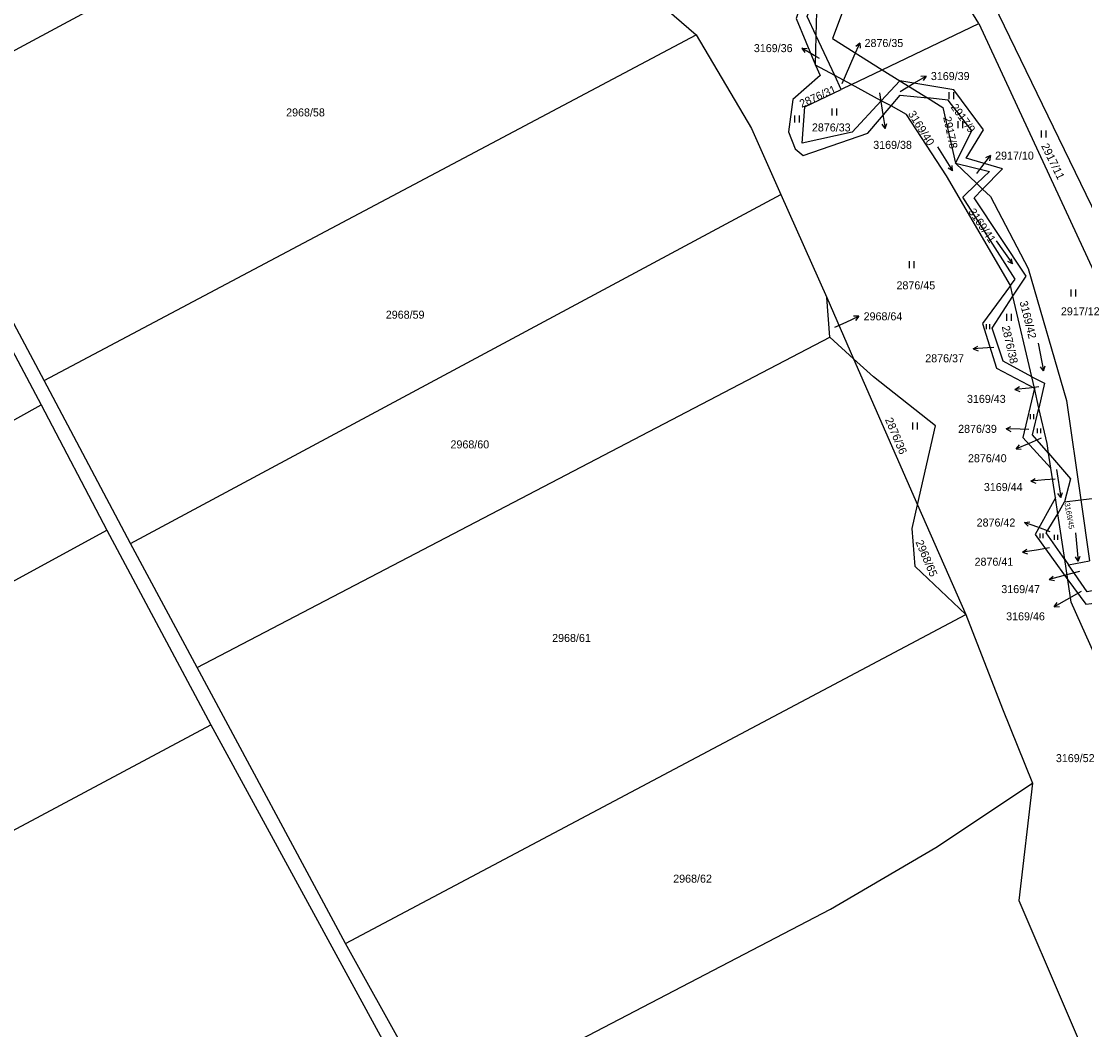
# Model space of a CAD drawing. Extents: x -776734 to -748832, y -1118122 to -976986.
# Drawn here: x -754304.9 to -754079.1, y -1114445.3 to -1114231.2 of the extents above; entities that cross this region are included whole.
import ezdxf

# ---------------------------------------------------------------- set-up
doc = ezdxf.new("R2010")
doc.units = 0
for name, color, linetype in [('KM_Hranice parcel', 7, 'Continuous'), ('KM_Parcelní čísla', 7, 'Continuous'), ('KM_Pop  PČ popisy', 7, 'Continuous'), ('KM_Značky kultur', 7, 'Continuous')]:
    doc.layers.add(name, color=color, linetype=linetype)

msp = doc.modelspace()

# ---------------------------------------------------------------- linework, layer by layer
at = {"layer": 'KM_Hranice parcel'}
for p, q in [((-754330.63, -1114250.42), (-754198.85, -1114179.51)), ((-754101.58, -1114231.65), (-754111.21, -1114215.97)), ((-754122.1, -1114241.5), (-754101.58, -1114231.65)), ((-754101.58, -1114231.65), (-754070.44, -1114298.96)), ((-754300.04, -1114307.5), (-754161.66, -1114234.11)), ((-754136.28, -1114240.53), (-754136.12, -1114234.32)), ((-754132.18, -1114242.74), (-754136.12, -1114234.32)), ((-754132.18, -1114242.74), (-754136.28, -1114240.53)), ((-754130.81, -1114245.67), (-754132.18, -1114242.74)), ((-754128.66, -1114244.64), (-754132.18, -1114242.74)), ((-754128.66, -1114244.64), (-754122.1, -1114241.5)), ((-754122.1, -1114241.5), (-754118.39, -1114243.82)), ((-754128.66, -1114244.64), (-754130.81, -1114245.67)), ((-754122.32, -1114248.07), (-754128.66, -1114244.64)), ((-754122.32, -1114248.07), (-754118.39, -1114243.82)), ((-754118.39, -1114243.82), (-754112.53, -1114247.49)), ((-754120.24, -1114249.19), (-754122.32, -1114248.07)), ((-754300.04, -1114307.5), (-754330.63, -1114250.42)), ((-754142.02, -1114254.7), (-754140.64, -1114258.27)), ((-754106.55, -1114261.3), (-754102, -1114265.68)), ((-754102, -1114265.68), (-754100.8, -1114266.84)), ((-754281.75, -1114342.09), (-754143.64, -1114268.01)), ((-754143.64, -1114268.01), (-754133.91, -1114289.88)), ((-754318.37, -1114279.49), (-754300.68, -1114312.68)), ((-754094.36, -1114289.61), (-754094.89, -1114287.34)), ((-754133.91, -1114289.88), (-754128.21, -1114302.87)), ((-754133.22, -1114298.26), (-754133.91, -1114289.88)), ((-754090.38, -1114306.73), (-754094.36, -1114289.61)), ((-754267.57, -1114368.44), (-754133.22, -1114298.26)), ((-754128.21, -1114302.87), (-754133.22, -1114298.26)), ((-754128.21, -1114302.87), (-754114.6, -1114333.87)), ((-754089.82, -1114309.14), (-754090.38, -1114306.73)), ((-754281.75, -1114342.09), (-754300.04, -1114307.5)), ((-754088.84, -1114313.35), (-754089.82, -1114309.14)), ((-754420.74, -1114378.33), (-754300.68, -1114312.68)), ((-754300.68, -1114312.68), (-754286.74, -1114339.26)), ((-754086.31, -1114326.08), (-754086.79, -1114322.92)), ((-754085.34, -1114332.43), (-754086.31, -1114326.08)), ((-754079.94, -1114332.85), (-754065.07, -1114330.98)), ((-754114.6, -1114333.87), (-754104.37, -1114357.19)), ((-754084.83, -1114335.76), (-754085.34, -1114332.43)), ((-754084.83, -1114335.76), (-754083.39, -1114333.28)), ((-754083.39, -1114333.28), (-754079.94, -1114332.85)), ((-754079.94, -1114332.85), (-754078.08, -1114345.79)), ((-754083.35, -1114345.47), (-754084.83, -1114335.76)), ((-754403.13, -1114402.7), (-754286.74, -1114339.26)), ((-754286.74, -1114339.26), (-754264.71, -1114380.62)), ((-754267.57, -1114368.44), (-754281.75, -1114342.09)), ((-754083.35, -1114345.47), (-754082.54, -1114346.65)), ((-754082.69, -1114349.83), (-754083.35, -1114345.47)), ((-754082.54, -1114346.65), (-754078.08, -1114345.79)), ((-754236.07, -1114427.01), (-754104.37, -1114357.19)), ((-754236.07, -1114427.01), (-754267.57, -1114368.44)), ((-754382.26, -1114443.46), (-754264.71, -1114380.62)), ((-754264.71, -1114380.62), (-754222.71, -1114457.49)), ((-754216.09, -1114463.01), (-754236.07, -1114427.01))]:
    msp.add_line(p, q, dxfattribs=at)
for points in [[(-754198.85, -1114179.51), (-754184.23, -1114198.03), (-754178.73, -1114219.2), (-754161.66, -1114234.11)], [(-754135.75, -1114198.57), (-754133.39, -1114209.08), (-754140.38, -1114230.64), (-754136.28, -1114240.53)], [(-754126, -1114206.49), (-754125.03, -1114209.47), (-754128.37, -1114223.34), (-754132.71, -1114234.86), (-754122.1, -1114241.5)], [(-754108.98, -1114205.82), (-754073.07, -1114279.85), (-754068.29, -1114298.13)], [(-754136.12, -1114234.32), (-754138.05, -1114230.19), (-754130.72, -1114210.04)], [(-754136.12, -1114234.32), (-754135.99, -1114229.21), (-754130.26, -1114212.66), (-754130.72, -1114210.04)], [(-754161.66, -1114234.11), (-754149.87, -1114253.99), (-754143.64, -1114268.01)], [(-754136.28, -1114240.53), (-754135.32, -1114242.74), (-754141.13, -1114247.79), (-754142.02, -1114254.7)], [(-754122.32, -1114248.07), (-754128.47, -1114254.73), (-754139.15, -1114257.08), (-754138.58, -1114249.4), (-754130.81, -1114245.67)], [(-754100.8, -1114266.84), (-754096.58, -1114262.54), (-754104.32, -1114260.28), (-754100.65, -1114254.25), (-754106.89, -1114245.75), (-754118.39, -1114243.82)], [(-754120.24, -1114249.19), (-754118.28, -1114246.9), (-754112.53, -1114247.49)], [(-754112.53, -1114247.49), (-754109.23, -1114249.55), (-754106.55, -1114261.3)], [(-754106.55, -1114261.3), (-754103.07, -1114254.47), (-754108.09, -1114247.94), (-754112.53, -1114247.49)], [(-754140.64, -1114258.27), (-754138.91, -1114259.72), (-754125.16, -1114254.96), (-754120.24, -1114249.19)], [(-754094.89, -1114287.34), (-754108.45, -1114264.04), (-754116.93, -1114250.98), (-754120.24, -1114249.19)], [(-754106.55, -1114261.3), (-754099.35, -1114263.1), (-754102, -1114265.68)], [(-754094.89, -1114287.34), (-754093.87, -1114285.98), (-754105, -1114268.59), (-754102, -1114265.68)], [(-754094.36, -1114289.61), (-754091.54, -1114285.34), (-754102.61, -1114268.68), (-754100.8, -1114266.84)], [(-754100.8, -1114266.84), (-754099.14, -1114268.43), (-754091.14, -1114283.7), (-754082.96, -1114311.7), (-754079.94, -1114332.85)], [(-754094.89, -1114287.34), (-754100.85, -1114295.35), (-754097.82, -1114304.86), (-754089.82, -1114309.14)], [(-754090.38, -1114306.73), (-754096.42, -1114303.38), (-754098.81, -1114296.34), (-754094.36, -1114289.61)], [(-754114.6, -1114333.87), (-754110.82, -1114317.14), (-754123.96, -1114306.73), (-754128.21, -1114302.87)], [(-754090.38, -1114306.73), (-754087.64, -1114308.03), (-754088.84, -1114313.35)], [(-754089.82, -1114309.14), (-754092.26, -1114319.57), (-754086.31, -1114326.08)], [(-754086.79, -1114322.92), (-754090.2, -1114319), (-754088.84, -1114313.35)], [(-754086.79, -1114322.92), (-754087.1, -1114320.85), (-754088.84, -1114313.35)], [(-754086.79, -1114322.92), (-754082.11, -1114328.38), (-754083.39, -1114333.28)], [(-754104.37, -1114357.19), (-754115.09, -1114347.01), (-754115.75, -1114338.93), (-754114.6, -1114333.87)], [(-754085.34, -1114332.43), (-754089.64, -1114340.17), (-754082.69, -1114349.83)], [(-754083.35, -1114345.47), (-754087.3, -1114339.82), (-754084.83, -1114335.76)], [(-754077.18, -1114352.09), (-754078.63, -1114352.33), (-754082.54, -1114346.65)], [(-754070.12, -1114390.62), (-754071.69, -1114377.62), (-754081.98, -1114354.52), (-754082.69, -1114349.83)], [(-754082.69, -1114349.83), (-754078.88, -1114355.01), (-754076.45, -1114354.67)], [(-754104.37, -1114357.19), (-754096.56, -1114377.22), (-754090.24, -1114392.95)], [(-754216.09, -1114463.01), (-754133.11, -1114419.74), (-754110.77, -1114406.63), (-754090.24, -1114392.95)], [(-754090.24, -1114392.95), (-754093.11, -1114417.93), (-754074.27, -1114461.78), (-754076.46, -1114473.86), (-754097.61, -1114489.99), (-754140.24, -1114510.72), (-754161.36, -1114513.79), (-754175.88, -1114510.05), (-754180.4, -1114509.3)]]:
    msp.add_lwpolyline(points, dxfattribs=at)
at = {"layer": 'KM_Pop  PČ popisy'}
for p, q in [((-754136.6, -1114238.44), (-754139.172, -1114236.894)), ((-754139.172, -1114236.894), (-754138.056, -1114236.981)), ((-754139.172, -1114236.894), (-754138.572, -1114237.839)), ((-754128.07, -1114238.57), (-754126.849, -1114235.828)), ((-754126.849, -1114235.828), (-754127.714, -1114236.54)), ((-754126.849, -1114235.828), (-754126.799, -1114236.947)), ((-754135.46, -1114239.11), (-754136.6, -1114238.44)), ((-754130.65, -1114244.44), (-754128.07, -1114238.57)), ((-754115.38, -1114244.36), (-754112.781, -1114242.86)), ((-754112.781, -1114242.86), (-754113.899, -1114242.927)), ((-754112.781, -1114242.86), (-754113.398, -1114243.794)), ((-754118.34, -1114246.1), (-754115.38, -1114244.36)), ((-754122.68, -1114246.42), (-754121.96, -1114251)), ((-754121.96, -1114251), (-754121.491, -1114253.964)), ((-754121.491, -1114253.964), (-754122.142, -1114253.053)), ((-754121.491, -1114253.964), (-754121.153, -1114252.897)), ((-754100.97, -1114262.11), (-754099.164, -1114259.713)), ((-754099.164, -1114259.713), (-754100.167, -1114260.212)), ((-754099.164, -1114259.713), (-754099.367, -1114260.814)), ((-754102.05, -1114263.52), (-754100.97, -1114262.11)), ((-754132.17, -1114296.19), (-754129.8, -1114295.11)), ((-754129.8, -1114295.11), (-754127.08, -1114293.842)), ((-754127.08, -1114293.842), (-754128.199, -1114293.811)), ((-754127.08, -1114293.842), (-754127.776, -1114294.719)), ((-754102.794, -1114300.789), (-754101.83, -1114300.22)), ((-754099.8, -1114300.58), (-754102.794, -1114300.789)), ((-754102.794, -1114300.789), (-754101.76, -1114301.219)), ((-754098.4, -1114300.49), (-754099.8, -1114300.58)), ((-754093.935, -1114309.394), (-754092.991, -1114308.791)), ((-754090.95, -1114309.08), (-754093.935, -1114309.394)), ((-754088.87, -1114308.86), (-754090.95, -1114309.08)), ((-754093.935, -1114309.394), (-754092.886, -1114309.787)), ((-754095.811, -1114317.768), (-754094.8, -1114317.284)), ((-754092.81, -1114317.82), (-754095.811, -1114317.768)), ((-754095.811, -1114317.768), (-754094.818, -1114318.286)), ((-754090.96, -1114317.86), (-754092.81, -1114317.82)), ((-754088.38, -1114319.76), (-754090.95, -1114320.83)), ((-754090.95, -1114320.83), (-754093.712, -1114322.003)), ((-754093.712, -1114322.003), (-754092.986, -1114321.15)), ((-754093.712, -1114322.003), (-754092.595, -1114322.072)), ((-754090.57, -1114328.852), (-754089.616, -1114328.265)), ((-754087.58, -1114328.59), (-754090.57, -1114328.852)), ((-754090.57, -1114328.852), (-754089.528, -1114329.263)), ((-754085.39, -1114328.41), (-754087.58, -1114328.59)), ((-754091.88, -1114337.634), (-754090.768, -1114337.506)), ((-754089.06, -1114338.66), (-754091.88, -1114337.634)), ((-754091.88, -1114337.634), (-754091.11, -1114338.447)), ((-754086.46, -1114339.59), (-754089.06, -1114338.66)), ((-754086.6, -1114343.05), (-754089.36, -1114343.49)), ((-754092.324, -1114343.959), (-754091.413, -1114343.308)), ((-754089.36, -1114343.49), (-754092.324, -1114343.959)), ((-754092.324, -1114343.959), (-754091.257, -1114344.297)), ((-754083.75, -1114348.98), (-754086.649, -1114349.757)), ((-754086.649, -1114349.757), (-754085.811, -1114349.014)), ((-754086.649, -1114349.757), (-754085.552, -1114349.981)), ((-754080.2, -1114348.01), (-754083.75, -1114348.98)), ((-754083.01, -1114354.06), (-754085.609, -1114355.56)), ((-754079.88, -1114352.26), (-754083.01, -1114354.06)), ((-754085.609, -1114355.56), (-754084.992, -1114354.626)), ((-754085.609, -1114355.56), (-754084.491, -1114355.493))]:
    msp.add_line(p, q, dxfattribs=at)
at = {"layer": 'KM_Značky kultur'}
for p, q in [((-754107.881, -1114247.75), (-754107.881, -1114246.25)), ((-754106.88, -1114247.75), (-754106.88, -1114246.25)), ((-754132.731, -1114251.24), (-754132.731, -1114249.74)), ((-754131.73, -1114251.24), (-754131.73, -1114249.74)), ((-754140.691, -1114252.73), (-754140.691, -1114251.23)), ((-754139.69, -1114252.73), (-754139.69, -1114251.23)), ((-754106.001, -1114253.89), (-754106.001, -1114252.39)), ((-754105, -1114253.89), (-754105, -1114252.39)), ((-754088.321, -1114255.91), (-754088.321, -1114254.41)), ((-754087.32, -1114255.91), (-754087.32, -1114254.41)), ((-754110.358, -1114257.855), (-754107.178, -1114262.943)), ((-754107.178, -1114262.943), (-754108.121, -1114262.38)), ((-754107.178, -1114262.943), (-754107.271, -1114261.849)), ((-754097.928, -1114277.822), (-754094.486, -1114282.736)), ((-754094.486, -1114282.736), (-754094.636, -1114281.648)), ((-754116.351, -1114283.62), (-754116.351, -1114282.12)), ((-754115.35, -1114283.62), (-754115.35, -1114282.12)), ((-754094.486, -1114282.736), (-754095.458, -1114282.224)), ((-754082.021, -1114289.67), (-754082.021, -1114288.17)), ((-754081.02, -1114289.67), (-754081.02, -1114288.17)), ((-754095.671, -1114294.82), (-754095.671, -1114293.32)), ((-754094.67, -1114294.82), (-754094.67, -1114293.32)), ((-754099.962, -1114296.55), (-754099.962, -1114295.545)), ((-754099.292, -1114296.55), (-754099.292, -1114295.545)), ((-754088.988, -1114299.534), (-754087.843, -1114305.423)), ((-754087.843, -1114305.423), (-754088.521, -1114304.56)), ((-754087.843, -1114305.423), (-754087.537, -1114304.368)), ((-754090.632, -1114315.66), (-754090.632, -1114314.655)), ((-754089.962, -1114315.66), (-754089.962, -1114314.655)), ((-754115.631, -1114317.87), (-754115.631, -1114316.37)), ((-754114.63, -1114317.87), (-754114.63, -1114316.37)), ((-754089.142, -1114318.69), (-754089.142, -1114317.685)), ((-754088.472, -1114318.69), (-754088.472, -1114317.685)), ((-754085.135, -1114326.405), (-754084.196, -1114332.331)), ((-754084.196, -1114332.331), (-754084.845, -1114331.445)), ((-754084.196, -1114332.331), (-754083.854, -1114331.288)), ((-754088.582, -1114340.98), (-754088.582, -1114339.975)), ((-754087.912, -1114340.98), (-754087.912, -1114339.975)), ((-754085.532, -1114341.29), (-754085.532, -1114340.285)), ((-754084.862, -1114341.29), (-754084.862, -1114340.285)), ((-754081.11, -1114339.844), (-754080.483, -1114345.812)), ((-754080.483, -1114345.812), (-754081.084, -1114344.892)), ((-754080.483, -1114345.812), (-754080.087, -1114344.787))]:
    msp.add_line(p, q, dxfattribs=at)

# ---------------------------------------------------------------- texts
at = {"layer": 'KM_Parcelní čísla'}
for s, p in [('3169/36', (-754149.373, -1114237.76)), ('2876/35', (-754125.87, -1114236.67)), ('3169/39', (-754111.79, -1114243.69)), ('2968/58', (-754248.69, -1114251.41)), ('2876/33', (-754137.05, -1114254.6)), ('3169/38', (-754124.03, -1114258.298)), ('2917/10', (-754098.15, -1114260.58)), ('2876/45', (-754119.09, -1114288.13)), ('2968/59', (-754227.53, -1114294.36)), ('2968/64', (-754126.07, -1114294.71)), ('2917/12', (-754084.18, -1114293.65)), ('2876/37', (-754112.983, -1114303.618)), ('3169/43', (-754104.123, -1114312.238)), ('2876/39', (-754106.003, -1114318.6)), ('2968/60', (-754213.79, -1114321.9)), ('2876/40', (-754103.913, -1114324.838)), ('3169/44', (-754100.536, -1114330.96)), ('2876/42', (-754102.073, -1114338.49)), ('2876/41', (-754102.513, -1114346.818)), ('3169/47', (-754096.833, -1114352.628)), ('3169/46', (-754095.803, -1114358.408)), ('2968/61', (-754192.21, -1114363)), ('3169/52', (-754085.243, -1114388.52)), ('2968/62', (-754166.5, -1114414.11))]:
    msp.add_text(s, height=1.7, dxfattribs=at).set_placement(p)
for s, height, rotation, p in [('2876/31', 1.7, 24, (-754139.234, -1114249.606)), ('3169/40', 1.7, 302, (-754116.71, -1114250.85)), ('2917/9', 1.7, 306, (-754107.667, -1114249.459)), ('2917/8', 1.7, 282, (-754109.181, -1114251.606)), ('2917/11', 1.7, 296, (-754088.423, -1114257.632)), ('3169/41', 1.7, 304, (-754103.894, -1114271.645)), ('3169/42', 1.7, 284, (-754092.964, -1114290.795)), ('2876/38', 1.7, 283, (-754096.758, -1114296.051)), ('2876/36', 1.7, 293, (-754121.562, -1114315.782)), ('3169/45', 1.14, 280, (-754083.426, -1114333.513)), ('2968/65', 1.7, 293, (-754115.092, -1114341.782))]:
    msp.add_text(s, height=height, rotation=rotation, dxfattribs=at).set_placement(p)

doc.saveas('drawing.dxf')
